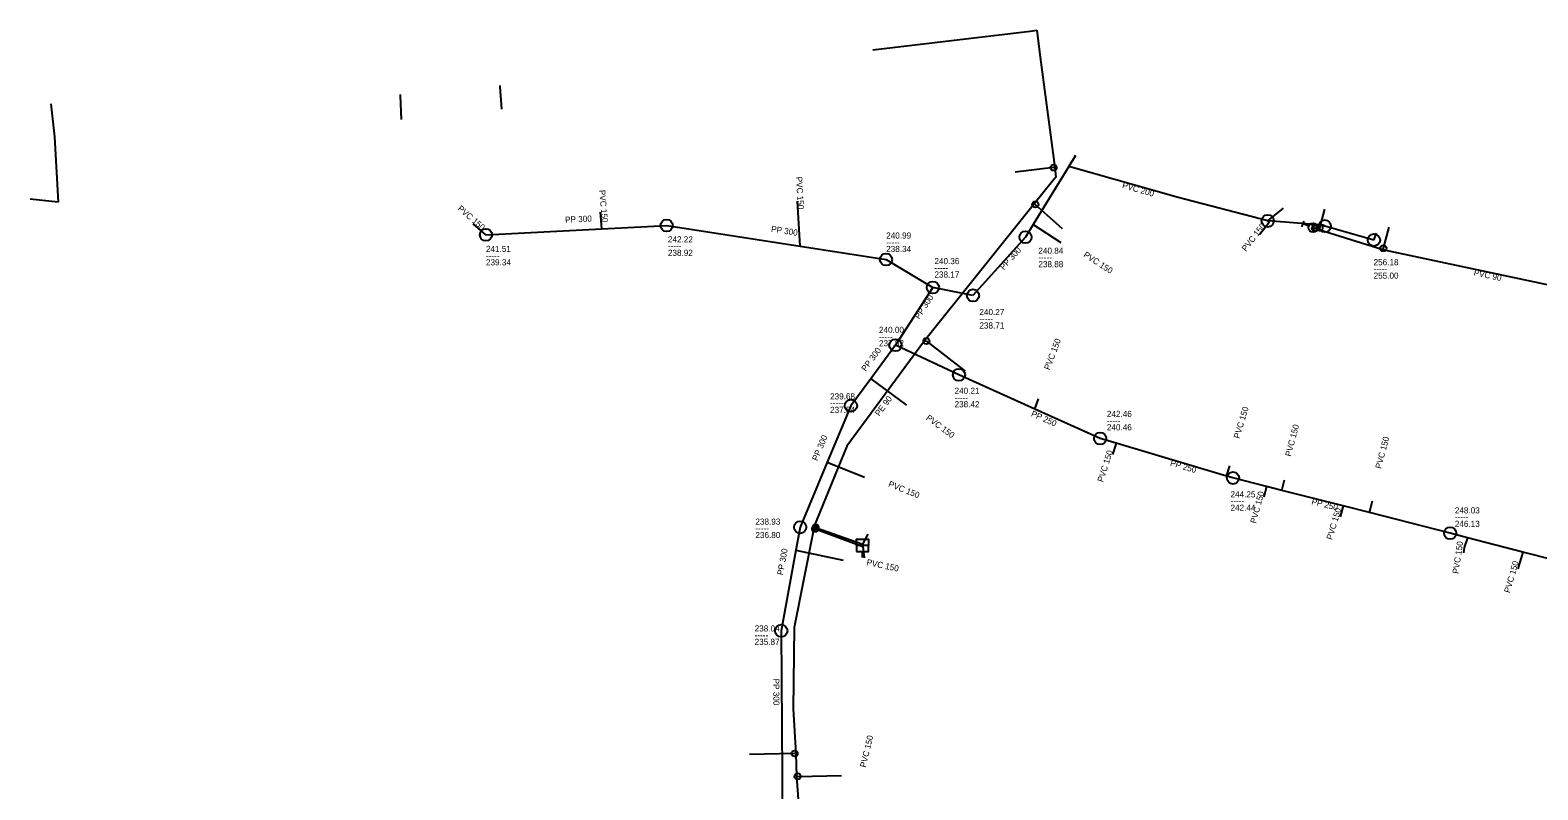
# Model space of a CAD drawing. Extents: x -771681 to -770485, y -1050143 to -1049574.
# Drawn here: x -771680.6 to -771433.4, y -1049804 to -1049679.5 of the extents above; entities that cross this region are included whole.
import ezdxf

# ---------------------------------------------------------------- set-up
doc = ezdxf.new("R2010")
doc.units = 0
doc.layers.add('Level 0', color=7, linetype='Continuous')

msp = doc.modelspace()

# ---------------------------------------------------------------- linework, layer by layer
at = {"layer": 'Level 0'}
for p, q in [((-771542.47, -1049682.73), (-771516.65, -1049679.66)), ((-771516.65, -1049679.66), (-771515.58, -1049679.51)), ((-771515.58, -1049679.51), (-771515.01, -1049683.95)), ((-771515.01, -1049683.95), (-771512.62, -1049702.01)), ((-771603.59, -1049688.58), (-771603.58, -1049688.78)), ((-771603.58, -1049688.78), (-771603.34, -1049692.47)), ((-771677.24, -1049691.59), (-771676.62, -1049697.01)), ((-771619.92, -1049690.05), (-771619.92, -1049690.25)), ((-771619.92, -1049690.25), (-771619.76, -1049694.16)), ((-771676.62, -1049697.01), (-771676.02, -1049707.67)), ((-771512.82, -1049702.03), (-771519.1, -1049702.76)), ((-771510.32, -1049701.84), (-771516.16, -1049711.36)), ((-771512.62, -1049702.01), (-771512.82, -1049702.03)), ((-771512.62, -1049702.01), (-771512.46, -1049703.6)), ((-771509.21, -1049700.03), (-771510.32, -1049701.84)), ((-771492.41, -1049706.94), (-771510.32, -1049701.84)), ((-771512.99, -1049704.24), (-771515.96, -1049707.93)), ((-771512.46, -1049703.6), (-771512.99, -1049704.24)), ((-771477.71, -1049710.77), (-771492.41, -1049706.94)), ((-771676.02, -1049707.67), (-771680.61, -1049707.18)), ((-771586.87, -1049712.06), (-771587.1, -1049709.34)), ((-771554.36, -1049714.9), (-771554.81, -1049707.51)), ((-771515.96, -1049707.93), (-771533.96, -1049730.4)), ((-771515.96, -1049707.93), (-771515.81, -1049708.06)), ((-771515.81, -1049708.06), (-771511.39, -1049712)), ((-771477.71, -1049710.77), (-771475.1, -1049708.67)), ((-771468.41, -1049708.82), (-771469.2, -1049711.9)), ((-771605.88, -1049713.05), (-771607.96, -1049711.25)), ((-771605.88, -1049713.05), (-771586.87, -1049712.06)), ((-771586.87, -1049712.06), (-771576.25, -1049711.51)), ((-771576.25, -1049711.51), (-771554.36, -1049714.9)), ((-771516.16, -1049711.36), (-771517.43, -1049713.43)), ((-771516.16, -1049711.36), (-771511.6, -1049714.33)), ((-771477.49, -1049711.04), (-771479.07, -1049713.07)), ((-771468.63, -1049711.48), (-771477.71, -1049710.77)), ((-771477.71, -1049710.77), (-771477.49, -1049711.04)), ((-771472.09, -1049711.73), (-771471.74, -1049710.79)), ((-771470.97, -1049711.6), (-771471.91, -1049711.26)), ((-771470.04, -1049712.57), (-771470.5, -1049711.15)), ((-771469.98, -1049712), (-771470.27, -1049711.86)), ((-771469.3, -1049712.21), (-771469.98, -1049712)), ((-771469.2, -1049711.9), (-771469.3, -1049712.21)), ((-771468.34, -1049711.61), (-771468.63, -1049711.48)), ((-771460.29, -1049713.9), (-771468.34, -1049711.61)), ((-771458.75, -1049715.25), (-771457.78, -1049711.79)), ((-771517.43, -1049713.43), (-771526.03, -1049722.97)), ((-771458.82, -1049715.48), (-771469.3, -1049712.21)), ((-771460.29, -1049713.9), (-771459.86, -1049712.79)), ((-771554.36, -1049714.9), (-771540.29, -1049717.09)), ((-771458.82, -1049715.48), (-771458.75, -1049715.25)), ((-771428.76, -1049721.9), (-771458.82, -1049715.48)), ((-771540.29, -1049717.09), (-771532.6, -1049721.68)), ((-771532.6, -1049721.68), (-771538.75, -1049731.12)), ((-771526.03, -1049722.97), (-771532.6, -1049721.68)), ((-771533.96, -1049730.4), (-771546.7, -1049747.67)), ((-771538.75, -1049731.12), (-771542.79, -1049736.62)), ((-771528.33, -1049735.99), (-771538.75, -1049731.12)), ((-771533.96, -1049730.4), (-771533.67, -1049730.46)), ((-771533.67, -1049730.46), (-771527.3, -1049735.38)), ((-771542.79, -1049736.62), (-771546.04, -1049741.04)), ((-771542.79, -1049736.62), (-771536.91, -1049740.98)), ((-771515.9, -1049741.59), (-771528.33, -1049735.99)), ((-771546.04, -1049741.04), (-771549.92, -1049750.32)), ((-771515.9, -1049741.59), (-771515.27, -1049739.93)), ((-771505.18, -1049746.42), (-771515.9, -1049741.59)), ((-771502.55, -1049747.2), (-771505.18, -1049746.42)), ((-771546.7, -1049747.67), (-771552.1, -1049760.87)), ((-771502.55, -1049747.2), (-771503.14, -1049749.03)), ((-771484.44, -1049752.58), (-771502.55, -1049747.2)), ((-771549.92, -1049750.32), (-771554.37, -1049760.96)), ((-771549.92, -1049750.32), (-771543.81, -1049752.76)), ((-771484.44, -1049752.58), (-771483.94, -1049750.92)), ((-771483.4, -1049752.89), (-771484.44, -1049752.58)), ((-771477.89, -1049754.29), (-771483.4, -1049752.89)), ((-771475.4, -1049754.92), (-771474.95, -1049753.18)), ((-771477.89, -1049754.29), (-771478.35, -1049756.03)), ((-771475.4, -1049754.92), (-771477.89, -1049754.29)), ((-771465.31, -1049757.48), (-771475.4, -1049754.92)), ((-771465.31, -1049757.48), (-771465.83, -1049759.23)), ((-771461.03, -1049758.57), (-771465.31, -1049757.48)), ((-771461.03, -1049758.57), (-771460.52, -1049756.63)), ((-771447.79, -1049761.93), (-771461.03, -1049758.57)), ((-771552.1, -1049761.17), (-771555.34, -1049777.41)), ((-771554.37, -1049760.96), (-771555.06, -1049764.74)), ((-771552.1, -1049760.87), (-771551.84, -1049760.99)), ((-771552.1, -1049760.87), (-771552.1, -1049761.17)), ((-771552.1, -1049761.17), (-771551.91, -1049761.24)), ((-771551.91, -1049761.24), (-771544.07, -1049764.1)), ((-771551.84, -1049760.99), (-771544.09, -1049763.72)), ((-771544.09, -1049763.72), (-771543.23, -1049762.1)), ((-771444.96, -1049762.67), (-771447.79, -1049761.93)), ((-771444.96, -1049762.67), (-771445.48, -1049764.29)), ((-771435.88, -1049765.03), (-771444.96, -1049762.67)), ((-771555.06, -1049764.74), (-771557.46, -1049777.92)), ((-771555.06, -1049764.74), (-771547.34, -1049766.35)), ((-771544.14, -1049765.94), (-771544.14, -1049764.94)), ((-771544.07, -1049764.1), (-771543.86, -1049765.97)), ((-771445.48, -1049764.29), (-771445.61, -1049765.17)), ((-771435.88, -1049765.03), (-771436.68, -1049767.77)), ((-771430.92, -1049766.32), (-771435.88, -1049765.03)), ((-771557.46, -1049777.92), (-771557.25, -1049809.4)), ((-771555.34, -1049777.41), (-771555.49, -1049790.71)), ((-771555.49, -1049790.71), (-771555.08, -1049798.03)), ((-771555.28, -1049798.04), (-771562.67, -1049798.21)), ((-771555.08, -1049798.03), (-771555.28, -1049798.04)), ((-771555.08, -1049798.03), (-771554.98, -1049801.78)), ((-771554.98, -1049801.78), (-771554.78, -1049801.78)), ((-771554.98, -1049801.78), (-771554.49, -1049808.55)), ((-771554.78, -1049801.78), (-771547.57, -1049801.64))]:
    msp.add_line(p, q, dxfattribs=at)
msp.add_lwpolyline([(-771545.14, -1049763.94), (-771545.14, -1049762.94), (-771543.14, -1049762.94), (-771543.14, -1049763.94)], dxfattribs=at)
msp.add_lwpolyline([(-771545.14, -1049764.94), (-771543.14, -1049764.94), (-771543.14, -1049763.94), (-771545.14, -1049763.94)], close=True, dxfattribs=at)
for centre, radius in [((-771512.82, -1049702.03), 0.5), ((-771515.81, -1049708.06), 0.5), ((-771605.88, -1049713.05), 1), ((-771576.25, -1049711.51), 1), ((-771477.71, -1049710.77), 1), ((-771470.27, -1049711.86), 0.75), ((-771469.98, -1049712), 0.5), ((-771469.2, -1049711.9), 0.5), ((-771468.34, -1049711.61), 1), ((-771517.43, -1049713.43), 1), ((-771460.29, -1049713.9), 1), ((-771540.29, -1049717.09), 1), ((-771458.75, -1049715.25), 0.5), ((-771532.6, -1049721.68), 1), ((-771526.03, -1049722.97), 1), ((-771538.75, -1049731.12), 1), ((-771533.67, -1049730.46), 0.5), ((-771528.33, -1049735.99), 1), ((-771546.04, -1049741.04), 1), ((-771505.18, -1049746.42), 1), ((-771483.4, -1049752.89), 1), ((-771554.37, -1049760.96), 1), ((-771551.91, -1049761.24), 0.5), ((-771551.84, -1049760.99), 0.5), ((-771447.79, -1049761.93), 1), ((-771557.46, -1049777.92), 1), ((-771555.28, -1049798.04), 0.5), ((-771554.78, -1049801.78), 0.5)]:
    msp.add_circle(centre, radius, dxfattribs=at)

# ---------------------------------------------------------------- texts
for s, rotation, p in [('PVC 150', 273.485, (-771555.05, -1049703.56)), ('PVC 200', 344.105, (-771501.64, -1049705.35)), ('PVC 150', 274.833, (-771587.32, -1049705.73)), ('PVC 150', 319.128, (-771610.61, -1049708.89)), ('PP 300', 2.965, (-771592.88, -1049711.09)), ('PP 300', 351.153, (-771559.18, -1049712.54)), ('PVC 150', 52.105, (-771481.27, -1049715.85)), ('PP 300', 47.966, (-771520.99, -1049718.87)), ('PVC 150', 326.923, (-771508.01, -1049716.55)), ('PVC 90', 347.944, (-771444, -1049719.67)), ('PP 300', 56.916, (-771534.84, -1049726.95)), ('PP 300', 53.673, (-771543.61, -1049735.51)), ('PVC 150', 69.217, (-771513.48, -1049735.28)), ('PE 90', 53.584, (-771541.39, -1049742.84)), ('PVC 150', 73.237, (-771482.36, -1049746.5)), ('PVC 150', 323.443, (-771533.82, -1049743.24)), ('PP 250', 335.747, (-771516.6, -1049742.71)), ('PVC 150', 75.5, (-771473.9, -1049749.44)), ('PP 300', 67.304, (-771551.53, -1049750.16)), ('PVC 150', 75.271, (-771459.13, -1049751.45)), ('PVC 150', 72.13, (-771504.71, -1049753.64)), ('PP 250', 343.455, (-771493.78, -1049750.85)), ('PVC 150', 338.231, (-771540, -1049754.26)), ('PVC 150', 75.192, (-771479.63, -1049760.41)), ('PP 250', 345.764, (-771470.6, -1049757.17)), ('PVC 150', 73.451, (-771467.15, -1049763.1)), ('PVC 150', 81.597, (-771446.44, -1049768.63)), ('PP 300', 79.68, (-771557.18, -1049768.86)), ('PVC 150', 348.22, (-771543.55, -1049767.15)), ('PVC 150', 73.724, (-771438.03, -1049771.8)), ('PP 300', 270.382, (-771558.79, -1049785.77)), ('PVC 150', 76.725, (-771543.6, -1049800.4))]:
    msp.add_text(s, height=1, rotation=rotation, dxfattribs=at).set_placement(p)
for s, p in [('242.22', (-771576.05, -1049714.29)), ('-----', (-771540.26, -1049714.76)), ('240.99', (-771540.26, -1049713.66)), ('-----', (-771605.88, -1049716.95)), ('241.51', (-771605.88, -1049715.85)), ('-----', (-771576.05, -1049715.39)), ('238.92', (-771576.05, -1049716.49)), ('238.34', (-771540.26, -1049715.86)), ('240.36', (-771532.35, -1049717.85)), ('-----', (-771515.31, -1049717.25)), ('240.84', (-771515.31, -1049716.15)), ('256.18', (-771460.35, -1049718.03)), ('239.34', (-771605.88, -1049718.05)), ('-----', (-771532.35, -1049718.95)), ('238.17', (-771532.35, -1049720.05)), ('238.88', (-771515.31, -1049718.35)), ('-----', (-771460.35, -1049719.13)), ('255.00', (-771460.35, -1049720.23)), ('-----', (-771524.98, -1049727.3)), ('240.27', (-771524.98, -1049726.2)), ('240.00', (-771541.44, -1049729.11)), ('238.71', (-771524.98, -1049728.4)), ('-----', (-771541.44, -1049730.21)), ('237.82', (-771541.44, -1049731.31)), ('239.68', (-771549.46, -1049740.02)), ('240.21', (-771529.05, -1049739.1)), ('-----', (-771549.46, -1049741.12)), ('237.54', (-771549.46, -1049742.22)), ('-----', (-771529.05, -1049740.2)), ('238.42', (-771529.05, -1049741.3)), ('-----', (-771504.08, -1049743.99)), ('242.46', (-771504.08, -1049742.89)), ('240.46', (-771504.08, -1049745.09)), ('244.25', (-771483.81, -1049756.06)), ('-----', (-771483.81, -1049757.16)), ('242.44', (-771483.81, -1049758.26)), ('248.03', (-771447.03, -1049758.7)), ('-----', (-771561.7, -1049761.64)), ('238.93', (-771561.7, -1049760.54)), ('-----', (-771447.03, -1049759.8)), ('246.13', (-771447.03, -1049760.9)), ('236.80', (-771561.7, -1049762.74)), ('-----', (-771561.83, -1049779.14)), ('238.04', (-771561.83, -1049778.04)), ('235.87', (-771561.83, -1049780.24))]:
    msp.add_text(s, height=1, dxfattribs=at).set_placement(p)

doc.saveas('drawing.dxf')
